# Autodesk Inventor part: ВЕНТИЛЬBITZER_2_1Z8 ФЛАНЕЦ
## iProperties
Created: 2011-02
Part Number: ВЕНТИЛЬBITZER_2_1Z8 ФЛАНЕЦ
Document SubType Name: Modeling
Designer: Чернышев Юрий
Mass: 216.893 g
Surface Area: 374.567 cm^2
Volume: 216.893 cm^3
Density: 1 g/cm^3
Author: Чернышев Юрий
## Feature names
1. ExtrusionBlind1
2. Hole1
3. Hole2
4. Hole3
5. Hole4
6. Hole5
